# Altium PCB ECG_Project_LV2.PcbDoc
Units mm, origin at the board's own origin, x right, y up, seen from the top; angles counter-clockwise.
Board outline 77.98 x 49.78 mm, 2 copper layers (Top Layer, Bottom Layer); 30 components, 21 nets, 88 pads, 0 vias.
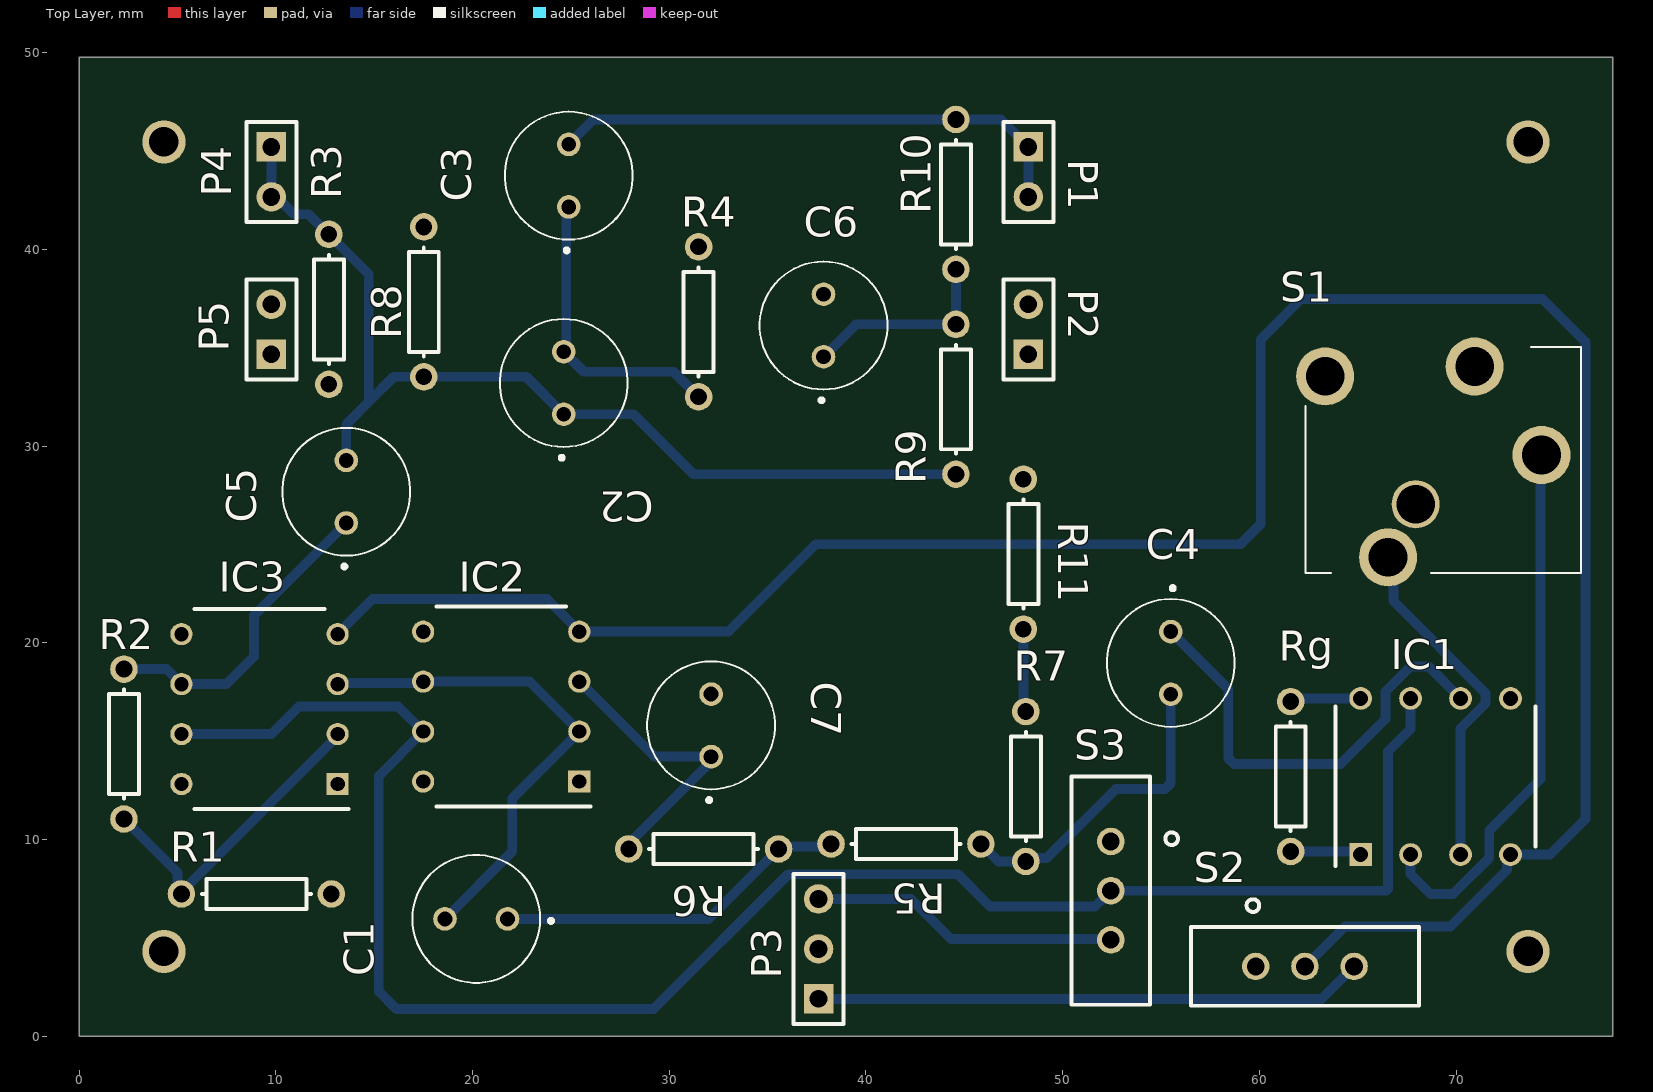
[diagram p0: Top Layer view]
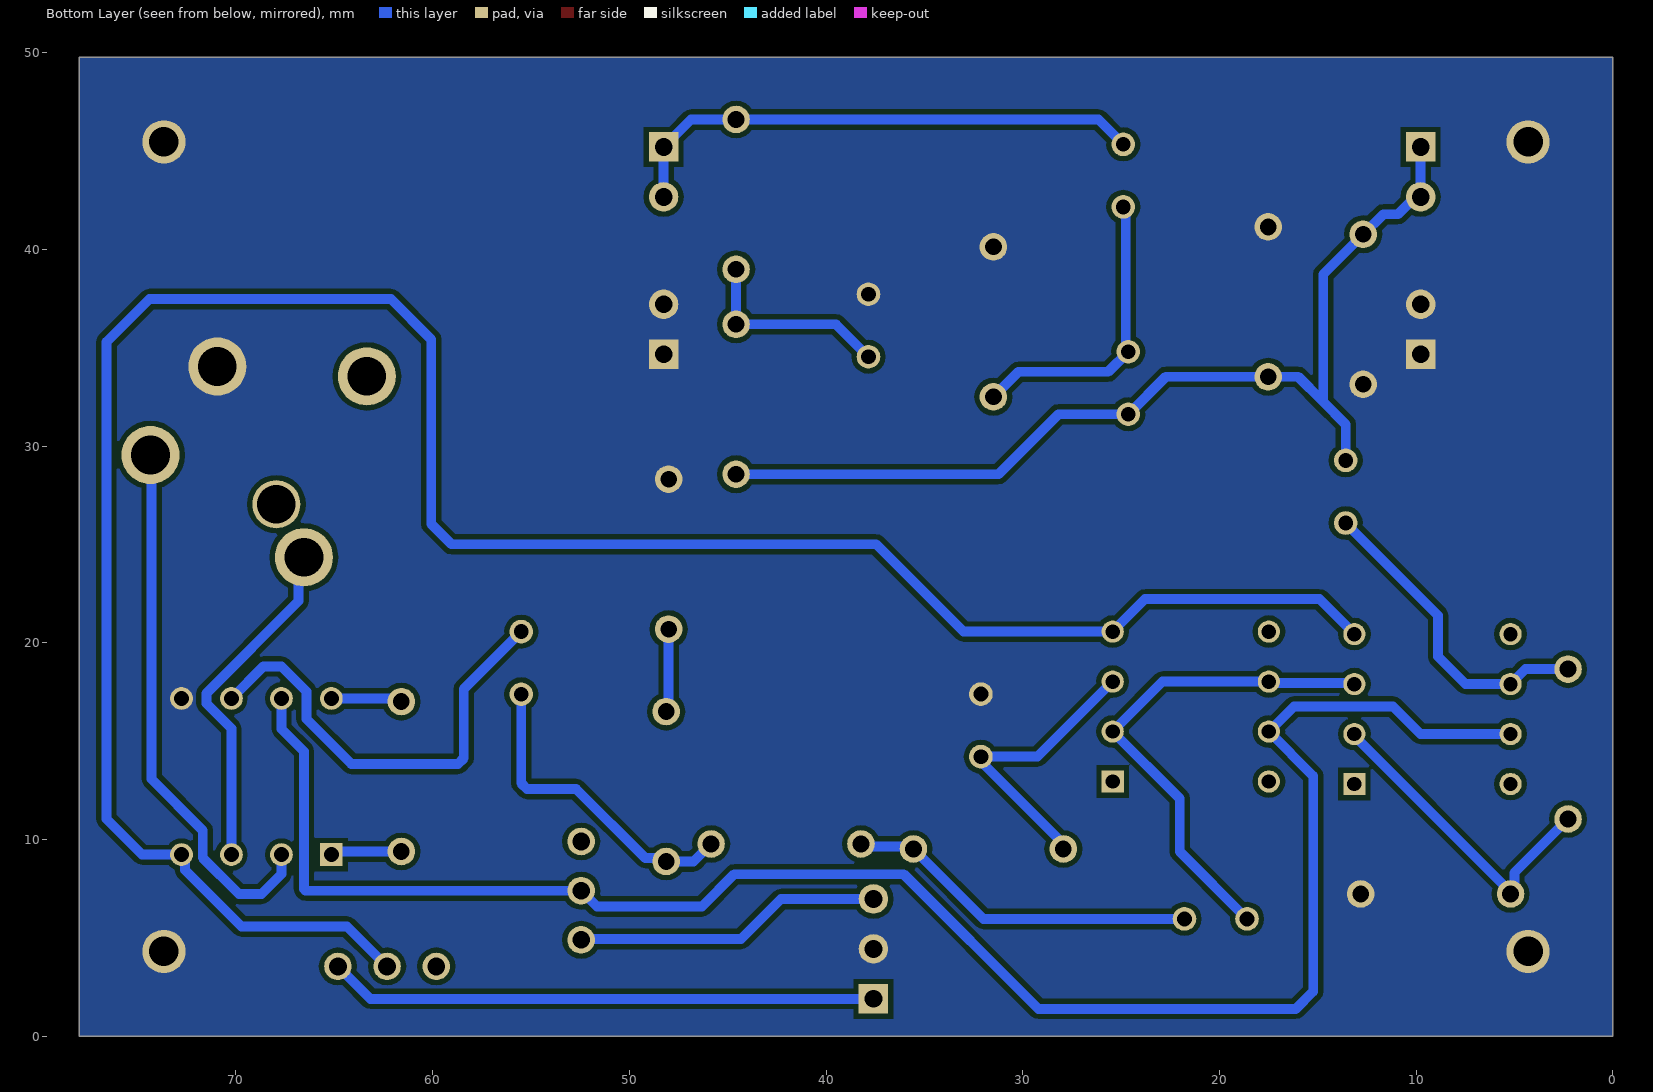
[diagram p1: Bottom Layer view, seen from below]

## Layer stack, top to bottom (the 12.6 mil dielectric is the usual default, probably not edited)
Top Solder: solder mask 0.0102, Solder Resist, Dk 3.5
Top Layer: signal copper 0.0356
Dielectric 1: dielectric 0.32, FR-4, Dk 4.8
Bottom Layer: signal copper 0.0356
Bottom Solder: solder mask 0.0102, Solder Resist, Dk 3.5

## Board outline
0,0 77.978,0 77.978,49.784 0,49.784

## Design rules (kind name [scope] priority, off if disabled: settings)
Clearance [All] p1: gap=0.254 ignorepadtopadclearanceinfootprint=FALSE except(0: Arc-Hole Track-Hole SMDPad-Hole THPad-Hole Via-Hole Fill-Hole Poly-Hole Region-Hole Text-Hole)
PolygonConnect [All] p1: connectstyle=Direct reliefconductorwidth=0.254 reliefentries=4 polygonreliefangle="90 Angle" airgapwidth=0.254
RoutingVias [All] p1: holewidth=0.711 width=1.27 viastyle="Through Hole" minholewidth=0.711 minwidth=1.27 maxholewidth=0.711 maxwidth=1.27
SolderMaskExpansion [All] p1: expansion=0.102
Width [All] p1: maxlimit=0.5 minlimit=0.5 preferedwidth=0.5
30 further rules are at their usual default settings.

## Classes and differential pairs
component class ECG_Project_LV2: C1 C2 C3 C4 C5 C6 C7 IC1 IC2 IC3 P1 P2 P3 P4 P5 R1 R2 R3 R4 R5 R6 R7 R8 R9 R10 R11 Rg S1

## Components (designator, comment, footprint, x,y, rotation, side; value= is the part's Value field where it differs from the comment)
C1 "1uF" TAP106K016GSB 20.193,5.969 r180 top
C2 "100nF" TAP106K016GSB 24.638,33.213 r90 top
C3 "100nF" TAP106K016GSB 24.892,43.754 r90 top
C4 "10uF" TAP106K016GSB 55.499,18.984 r270 top
C5 "10uF" TAP106K016GSB 13.589,27.686 r90 top
C6 "220nF" TAP106K016GSB 37.846,36.134 r90 top
C7 "1uF" TAP106K016GSB 32.131,15.809 r90 top
IC1 "AD620AN" DIP794W56P254L959H533Q8N 68.961,13.208 r90 top
IC2 "LF411ACN_NOPB" DIP794W53P254L959H508Q8N 21.463,16.764 r180 top
IC3 "LM741CN" DIP794W53P254L959H508Q8N 9.177,16.637 r180 top
P1 "Output" HDR1X2 48.26,45.212 r270 top
P2 "OutputGround" HDR1X2 48.26,34.671 r90 top
P3 "Power" HDR1X3 37.592,1.905 r90 top
P4 "Output" HDR1X2 9.779,45.212 r270 top
P5 "OutputGround" HDR1X2 9.779,34.671 r90 top
R1 "Res1" AXIAL-0.3 9.017,7.239 r0 top value=1K
R2 "Res1" AXIAL-0.3 2.286,14.859 r90 top value=22K
R3 "Res1" AXIAL-0.3 12.7,36.957 r270 top value=15K
R4 "Res1" AXIAL-0.3 31.496,36.322 r270 top value=15K
R5 "Res1" AXIAL-0.3 42.037,9.779 r180 top value=8.04K
R6 "Res1" AXIAL-0.3 31.75,9.525 r180 top value=8.04K
R7 "Res1" AXIAL-0.3 48.133,12.7 r270 top value=150K
R8 "Res1" AXIAL-0.3 17.526,37.338 r270 top value=22K
R9 "Res1" AXIAL-0.3 44.577,32.385 r90 top value=33K
R10 "Res1" AXIAL-0.3 44.577,42.799 r90 top value=33K
R11 "Res1" AXIAL-0.3 48.006,24.511 r270 top value=8.4K
Rg "Res1" AXIAL-0.3 61.595,13.208 r90 top value=560
S1 "35RAPC4BH3" 35RAPC4BH3 74.345,29.551 r180 top
S2 "EG1218" 3PIN_SLIDE_SWITCH 62.317,3.556 r0 top
S3 "EG1218" 3PIN_SLIDE_SWITCH 52.451,7.406 r270 top

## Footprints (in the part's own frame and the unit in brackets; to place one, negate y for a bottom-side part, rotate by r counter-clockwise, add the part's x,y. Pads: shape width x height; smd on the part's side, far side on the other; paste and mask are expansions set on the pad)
3PIN_SLIDE_SWITCH [mm]
  round 1.4 hole 0.9: 1(-2.5,0) 2(0,0) 3(2.5,0)
  silkscreen extent -5.8,-2 5.8,3.41
35RAPC4BH3 [mm]
  round 2.955 hole 1.97: 1(0,0) 2(7.8,5.2) 4(11,-4) 5(3.4,-4.5)
  round 2.447 hole 1.97: 3(6.4,2.5)
  silkscreen extent -2,-5.5 12,6
AXIAL-0.3 [mm] "Axial Device, Thru-Hole; 2 Leads; 0.3 in Pin Spacing"
  round 1.4 hole 0.85: 1(-3.81,0) 2(3.81,0)
  silkscreen extent -2.77,-0.76 2.77,0.76
DIP794W53P254L959H508Q8N [mm]
  rect 1.13x1.13 hole 0.73: 1(-3.97,3.81)
  round 1.13 hole 0.73: 2(-3.97,1.27) 3(-3.97,-1.27) 4(-3.97,-3.81) 5(3.97,-3.81) 6(3.97,-1.27) 7(3.97,1.27) 8(3.97,3.81)
  silkscreen extent -4.53,-5.08 3.3,5.08, body extent -4.1,-4.79 4.1,4.79, height 5.08
DIP794W56P254L959H533Q8N [mm]
  rect 1.16x1.16 hole 0.76: 1(-3.97,3.81)
  round 1.16 hole 0.76: 2(-3.97,1.27) 3(-3.97,-1.27) 4(-3.97,-3.81) 5(3.97,-3.81) 6(3.97,-1.27) 7(3.97,1.27) 8(3.97,3.81)
  silkscreen extent -4.55,-5.08 3.55,5.08, body extent -4.11,-4.79 4.11,4.79, height 5.33
HDR1X2 [mm] "Connector; Header; 2 Position"
  rect 1.5x1.5 hole 0.9: 1(0,0)
  round 1.5 hole 0.9: 2(2.54,0)
  silkscreen extent -1.27,-1.27 3.81,1.27
HDR1X3 [mm] "Connector; Header; 3 Position"
  rect 1.5x1.5 hole 0.9: 1(0,0)
  round 1.5 hole 0.9: 2(2.54,0) 3(5.08,0)
  silkscreen extent -1.27,-1.27 6.35,1.27
TAP106K016GSB [mm]
  round 1.2 hole 0.75: 1(-1.59,0) 2(1.59,0)
  silkscreen extent -3.9,-3.25 3.25,3.25

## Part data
C1 C2 C3 C4 C5 C6 C7: library part TAP106K016GSB, "Capacitor", Manufacturer_Name=AVX, Mouser Part Number=581-TAP106K016GSB
IC1: "Integrated Circuit", Manufacturer_Name="Analog Devices", Mouser Part Number=584-AD620AN, RS Part Number=3695803
IC2: "Integrated Circuit", Manufacturer_Name="Texas Instruments", Manufacturer_Part_Number=LF411ACN/NOPB, Mouser Part Number=926-LF411ACN/NOPB, RS Part Number=5339246P
IC3: "Integrated Circuit", Manufacturer_Name="Texas Instruments", Mouser Part Number=926-LM741CN, RS Part Number=4718749
P1 P2 P4 P5: library part "Header 2", "Header, 2-Pin"
P3: library part "Header 3", "Header, 3-Pin"
R1 R2 R3 R4 R5 R6 R7 R8 R9 R10 R11 Rg: "Resistor"
S1: "Switch", Manufacturer_Name=Switchcraft, Mouser Part Number=502-35RAPC4BH3, RS Part Number=8787229
S2 S3: "Switch", Manufacturer_Name=E-Switch, Mouser Part Number=612-EG1218

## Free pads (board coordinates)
  round 2.2 hole 1.5: 6(4.318,4.318) 7(73.66,4.318) 8(73.66,45.466) 9(4.318,45.466)

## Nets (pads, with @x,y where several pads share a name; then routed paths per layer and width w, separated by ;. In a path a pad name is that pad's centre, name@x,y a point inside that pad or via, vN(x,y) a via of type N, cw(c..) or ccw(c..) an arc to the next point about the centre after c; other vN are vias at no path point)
+: C7.1 IC2.3 R6.2 | length 14.7
  Bottom Layer w0.5: IC2.3 29.248,14.219 C7.1 32.131,13.968 27.94,9.777 R6.2
+3.7: P3.3 S3.3 | length 15.7
  Bottom Layer w0.5: P3.3 42.291,6.985 44.323,4.953 52.404,4.953 S3.3
+Supply: IC1.7 IC2.7 IC3.7 S3.2 | length 93.2
  Bottom Layer w0.5: IC3.7 9.779,15.367 11.176,16.764 16.223,16.764 IC2.7 15.24,13.241 15.24,2.286 16.129,1.397 29.21,1.397 36.052,8.239 44.674,8.239 46.309,6.604 51.649,6.604 S3.2 66.461,7.406 66.548,7.493 66.548,14.478 67.691,15.621 IC1.7
-3.7: P3.1 S2.3 | length 27.9
  Bottom Layer w0.5: P3.1 63.166,1.905 S2.3
-IN: IC1.2 S1.1 | length 27.7
  Bottom Layer w0.5: IC1.2 67.691,8.255 68.707,7.239 69.85,7.239 71.687,9.076 71.687,10.473 74.295,13.081 74.295,29.501 S1.1
-Supply: IC1.4 IC2.4 IC3.4 S2.2 | length 120.2
  Bottom Layer w0.5: IC3.4 14.925,22.225 23.782,22.225 IC2.4 33.02,20.574 37.465,25.019 59.055,25.019 60.071,26.035 60.071,35.433 62.125,37.487 74.4,37.487 76.581,35.306 76.581,11.049 74.77,9.238 IC1.4 72.598,9.065 72.598,8.463 69.723,5.588 64.349,5.588 S2.2
GND: C6.2 C7.2 IC1.5 P2.1 P2.2 P3.2 P5.1 P5.2 pad.6 pad.7 pad.8 pad.9 R1.2 R3.2 R4.1 R8.1 R11.1 S1.5
NetC1_1: C1.1 R5.2 R6.1 | length 18
  Bottom Layer w0.5: C1.1 32.004,5.969 R6.1 35.687,9.652 38.1,9.652 R5.2
NetC1_2: C1.2 IC2.2 IC2.6 IC3.3 | length 25.7
  Bottom Layer w0.5: IC3.3 13.21,17.97 17.43,17.97 IC2.6 22.893,18.034 IC2.2 22.025,12.086 22.025,9.391 C1.2
NetC2_1: C2.1 C5.2 P4.1 P4.2 R3.1 R8.2 R9.1 | length 51.4
  Bottom Layer w0.5: P4.1 P4.2 10.05,42.672 10.929,41.792 11.675,41.792 R3.1 14.732,38.735 14.732,32.385 14.795,32.322 ; C5.2 13.589,31.115 14.795,32.322 ; R9.1 31.242,28.575 28.194,31.623 C2.1 22.733,33.528 R8.2 16.002,33.528 14.795,32.322
NetC2_2: C2.2 C3.1 R4.2 | length 15.3
  Bottom Layer w0.5: C3.1 24.765,42.037 24.765,34.93 C2.2 25.659,33.782 30.226,33.782 R4.2
NetC3_2: C3.2 P1.1 P1.2 R10.2 | length 27
  Bottom Layer w0.5: C3.2 26.157,46.609 R10.2 46.863,46.609 P1.1 P1.2
NetC4_1: C4.1 IC1.6 | length 23.1
  Bottom Layer w0.5: C4.1 58.42,17.653 58.42,14.136 58.713,13.843 64.135,13.843 66.421,16.129 66.421,17.526 67.691,18.796 68.613,18.796 IC1.6
NetC4_2: C4.2 R5.1 R7.2 | length 16.2
  Bottom Layer w0.5: R5.1 46.736,8.89 R7.2 48.305,9.062 49.194,9.062 52.705,12.573 55.206,12.573 55.499,12.866 C4.2
NetC5_1: C5.1 IC3.6 R2.2 | length 16.2
  Bottom Layer w0.5: R2.2 4.445,18.669 IC3.6 7.493,17.907 8.89,19.304 8.89,21.397 C5.1
NetC6_1: C6.1 R9.2 R10.1 | length 10.2
  Bottom Layer w0.5: C6.1 39.497,36.195 R9.2 R10.1
NetIC1_1: IC1.1 Rg.1 | length 3.6
  Bottom Layer w0.5: Rg.1 64.991,9.398 IC1.1
NetIC1_3: IC1.3 S1.2 | length 17.7
  Bottom Layer w0.5: S1.2 66.819,24.077 66.819,22.124 71.501,17.441 71.501,16.915 70.231,15.645 IC1.3
NetIC1_8: IC1.8 Rg.2 | length 3.6
  Bottom Layer w0.5: Rg.2 61.755,17.178 IC1.8
NetIC3_2: IC3.2 R1.1 R2.1 | length 16.4
  Bottom Layer w0.5: R2.1 5.015,8.32 5.015,7.431 R1.1 5.207,7.333 13.147,15.273 IC3.2
NetR7_1: R7.1 R11.2 | length 4.2
  Bottom Layer w0.5: R11.2 48.006,16.637 R7.1
pads on no net: IC2.1 IC2.5 IC2.8 IC3.1 IC3.5 IC3.8 S1.3 S1.4 S2.1 S3.1

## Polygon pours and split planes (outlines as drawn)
GND on Bottom Layer "Bottom Layer-GND" (solid, pour order 0): 0,0 0,49.784 77.93,49.784 77.93,0

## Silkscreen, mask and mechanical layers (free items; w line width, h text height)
Mechanical 2:
  lines w1: 0,0 76.708,0 77.978,0 77.978,49.784 76.708,49.784 0,49.784 0,0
